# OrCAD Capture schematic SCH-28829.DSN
size B; title: FRDM-CD1030EVM; rev: A; company: Freescale Semiconductor; note: SCH-28829 PDF: SPF-28829; note: 6501 William Cannon Drive West; note: Austin, TX 78735-8598
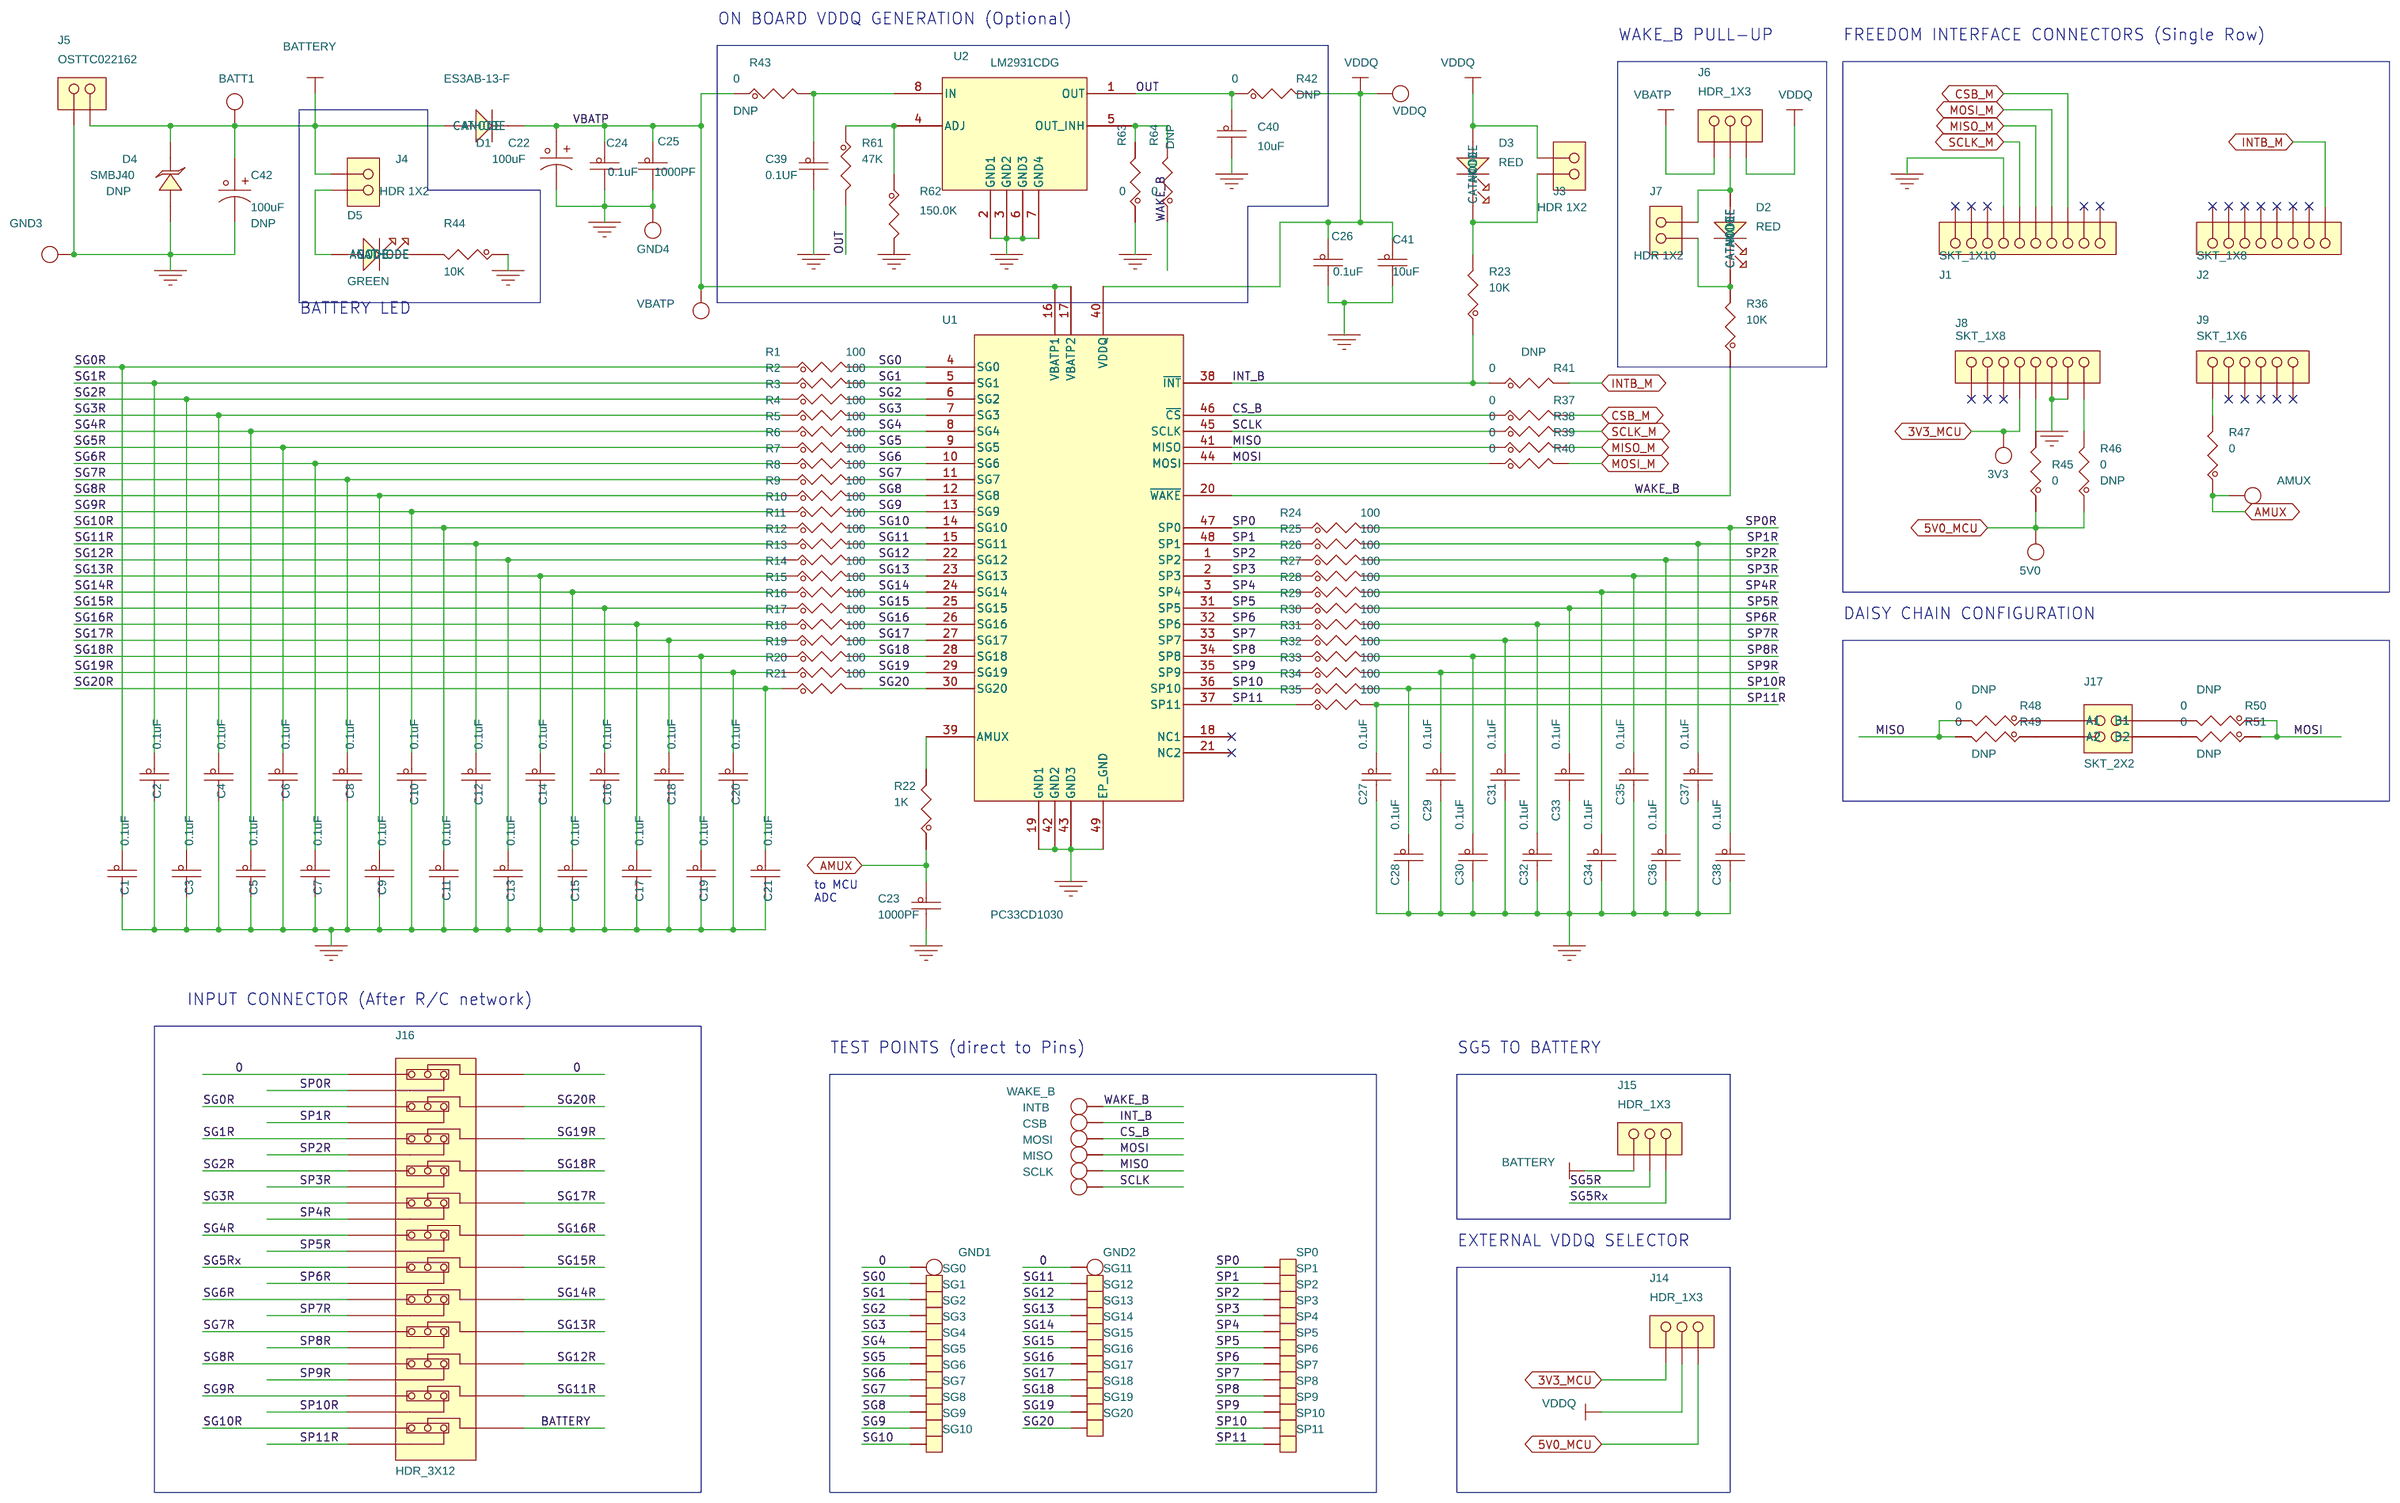
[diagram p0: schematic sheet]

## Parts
3V3  TEST POINT RED  [TEST_LOOP]
5V0  TEST POINT RED  [TEST_LOOP]
AMUX  TEST POINT RED  [TEST_LOOP]
BATT1  TEST POINT RED  [TEST_LOOP]
C1  0.1uF  [CC0603_OV]
C2  0.1uF  [CC0603_OV]
C3  0.1uF  [CC0603_OV]
C4  0.1uF  [CC0603_OV]
C5  0.1uF  [CC0603_OV]
C6  0.1uF  [CC0603_OV]
C7  0.1uF  [CC0603_OV]
C8  0.1uF  [CC0603_OV]
C9  0.1uF  [CC0603_OV]
C10  0.1uF  [CC0603_OV]
C11  0.1uF  [CC0603_OV]
C12  0.1uF  [CC0603_OV]
C13  0.1uF  [CC0603_OV]
C14  0.1uF  [CC0603_OV]
C15  0.1uF  [CC0603_OV]
C16  0.1uF  [CC0603_OV]
C17  0.1uF  [CC0603_OV]
C18  0.1uF  [CC0603_OV]
C19  0.1uF  [CC0603_OV]
C20  0.1uF  [CC0603_OV]
C21  0.1uF  [CC0603_OV]
C22  100uF  [cce8p3x8p3]
C23  1000PF  [CC0603_OV]
C24  0.1uF  [CC0603_OV]
C25  1000PF  [CC0603_OV]
C26  0.1uF  [CC0603_OV]
C27  0.1uF  [CC0603_OV]
C28  0.1uF  [CC0603_OV]
C29  0.1uF  [CC0603_OV]
C30  0.1uF  [CC0603_OV]
C31  0.1uF  [CC0603_OV]
C32  0.1uF  [CC0603_OV]
C33  0.1uF  [CC0603_OV]
C34  0.1uF  [CC0603_OV]
C35  0.1uF  [CC0603_OV]
C36  0.1uF  [CC0603_OV]
C37  0.1uF  [CC0603_OV]
C38  0.1uF  [CC0603_OV]
C39  0.1UF  [CC0603_OV]
C40  10uF  [CC1206_OV]
C41  10uF  [CC0805_OV]
C42  100uF  [cce8p3x8p3]
CSB  TEST POINT RED  [TEST_LOOP]
D1  ES3AB-13-F  [smb_4p57x3p94mm]
D2  RED  [led_2p_0805]
D3  RED  [led_2p_0805]
D4  SMBJ40  [DO-214AA_A]
D5  GREEN  [led2_2p34_2p1x1p25]
GND1  TEST POINT BLACK  [TEST_LOOP]
GND2  TEST POINT BLACK  [TEST_LOOP]
GND3  TEST POINT BLACK  [TEST_LOOP]
GND4  TEST POINT BLACK  [TEST_LOOP]
INTB  TEST POINT RED  [TEST_LOOP]
J1  SKT_1X10  [con_skt1x10_th]
J2  SKT_1X8  [con_skt1x8_th]
J3  HDR 1X2  [HDR102]
J4  HDR 1X2  [HDR102]
J5  OSTTC022162  [con2_tb_5p08_th_osttc]
J6  HDR_1X3  [HDR103]
J7  HDR 1X2  [HDR102]
J8  SKT_1X8  [con_skt1x8_th]
J9  SKT_1X6  [con_skt1x6_th]
J14  HDR_1X3  [HDR103]
J15  HDR_1X3  [HDR103]
J16  HDR_3X12  [hdr_3x12_100_th]
J17  SKT_2X2  [skt2x2_th_ssq]
MISO  TEST POINT RED  [TEST_LOOP]
MOSI  TEST POINT RED  [TEST_LOOP]
R1  100  [RC0805_OV]
R2  100  [RC0805_OV]
R3  100  [RC0805_OV]
R4  100  [RC0805_OV]
R5  100  [RC0805_OV]
R6  100  [RC0805_OV]
R7  100  [RC0805_OV]
R8  100  [RC0805_OV]
R9  100  [RC0805_OV]
R10  100  [RC0805_OV]
R11  100  [RC0805_OV]
R12  100  [RC0805_OV]
R13  100  [RC0805_OV]
R14  100  [RC0805_OV]
R15  100  [RC0805_OV]
R16  100  [RC0805_OV]
R17  100  [RC0805_OV]
R18  100  [RC0805_OV]
R19  100  [RC0805_OV]
R20  100  [RC0805_OV]
R21  100  [RC0805_OV]
R22  1K  [RC0805_OV]
R23  10K  [RC0805_OV]
R24  100  [RC0805_OV]
R25  100  [RC0805_OV]
R26  100  [RC0805_OV]
R27  100  [RC0805_OV]
R28  100  [RC0805_OV]
R29  100  [RC0805_OV]
R30  100  [RC0805_OV]
R31  100  [RC0805_OV]
R32  100  [RC0805_OV]
R33  100  [RC0805_OV]
R34  100  [RC0805_OV]
R35  100  [RC0805_OV]
R36  10K  [RC0805_OV]
R37  0  [RC0603_OV]
R38  0  [RC0603_OV]
R39  0  [RC0603_OV]
R40  0  [RC0603_OV]
R41  0  [RC0603_OV]
R42  0  [RC0603_OV]
R43  0  [RC0603_OV]
R44  10K  [RC0805_OV]
R45  0  [RC0603_OV]
R46  0  [RC0603_OV]
R47  0  [RC0603_OV]
R48  0  [RC0603_OV]
R49  0  [RC0603_OV]
R50  0  [RC0603_OV]
R51  0  [RC0603_OV]
R61  47K  [RC0603_OV]
R62  150.0K  [RC0603_OV]
R63  0  [RC0603_OV]
R64  0  [RC0603_OV]
SCLK  TEST POINT RED  [TEST_LOOP]
SG0  TH  [mst_testpoint]
SG1  TH  [mst_testpoint]
SG2  TH  [mst_testpoint]
SG3  TH  [mst_testpoint]
SG4  TH  [mst_testpoint]
SG5  TH  [mst_testpoint]
SG6  TH  [mst_testpoint]
SG7  TH  [mst_testpoint]
SG8  TH  [mst_testpoint]
SG9  TH  [mst_testpoint]
SG10  TH  [mst_testpoint]
SG11  TH  [mst_testpoint]
SG12  TH  [mst_testpoint]
SG13  TH  [mst_testpoint]
SG14  TH  [mst_testpoint]
SG15  TH  [mst_testpoint]
SG16  TH  [mst_testpoint]
SG17  TH  [mst_testpoint]
SG18  TH  [mst_testpoint]
SG19  TH  [mst_testpoint]
SG20  TH  [mst_testpoint]
SP0  TH  [mst_testpoint]
SP1  TH  [mst_testpoint]
SP2  TH  [mst_testpoint]
SP3  TH  [mst_testpoint]
SP4  TH  [mst_testpoint]
SP5  TH  [mst_testpoint]
SP6  TH  [mst_testpoint]
SP7  TH  [mst_testpoint]
SP8  TH  [mst_testpoint]
SP9  TH  [mst_testpoint]
SP10  TH  [mst_testpoint]
SP11  TH  [mst_testpoint]
U1  PC33CD1030  [LQFP48_EP146MIL]
U2  LM2931CDG  [SO8_1P27_4X5]
VBATP  TEST POINT RED  [TEST_LOOP]
VDDQ  TEST POINT RED  [TEST_LOOP]
WAKE_B  TEST POINT RED  [TEST_LOOP]

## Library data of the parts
3V3 5V0 AMUX BATT1 CSB INTB MISO MOSI SCLK VBATP VDDQ WAKE_B = TestLoop: TEST POINT RED 40 MIL DRILL 180 MIL TH 109L; AGILE_PN: 210-75684; CAD_APPROVED: Yes; HEIGHT: 4.8 MM; MFG_NAME01: KEYSTONE ELECTRONICS; MFG_PN01: 5000; ROHS: Yes
C1-C21 C24 C26-C38 = CAP_NP: CAP CER 0.1uF 100V X7R 10% 0603; AGILE_PN: 150-79200; CAD_APPROVED: Yes; FPLIST: CC0603_OV,CC0603,0603_CC; HEIGHT: 0.9MM; MFG_NAME01: Murata; MFG_PN01: GRM188R72A104KA35D; ROHS: Yes; Tolerance: 10%; VOLTAGE: 100V
C22 = CAP_POL: CAP ALEL 100uF 50V 20% -- SMD; AGILE_PN: 150-79137; CAD_APPROVED: Yes; HEIGHT: 10.5MM; MFG_NAME01: NICHICON; MFG_PN01: UUD1H101MNL1GS; ROHS: Yes; Tolerance: 20%; VOLTAGE: 50V
C23 C25 = CAP_NP: CAP CER 1000PF 100V 10% X7R 0603; AGILE_PN: 150-77156; CAD_APPROVED: Yes; FPLIST: CC0603_OV,CC0603,0603_CC; HEIGHT: 0.95MM; MFG_NAME01: KEMET; MFG_PN01: C0603C102K1RACTU; ROHS: Yes; Tolerance: 10%; VOLTAGE: 100V
C39 = CAP_NP: CAP CER 0.1UF 50V 10% X7R 0603; AGILE_PN: 150-75142; CAD_APPROVED: Yes; FPLIST: CC0603_OV,CC0603,0603_CC; HEIGHT: 0.9652MM; MFG_NAME01: AVX; MFG_PN01: 06035C104KAT2A; ROHS: Yes; Tolerance: 10%; VOLTAGE: 50V
C40 = CAP_NP: CAP CER 10uF 25V 10% X7R 1206; AGILE_PN: 150-79147; CAD_APPROVED: Yes; FPLIST: CC1206_OV,CC1206,1206_CC; HEIGHT: 1.8MM; MFG_NAME01: Murata; MFG_PN01: GRM31CR71E106KA12; ROHS: Yes; Tolerance: 10%; VOLTAGE: 25V
C41 = CAP_NP: CAP CER 10UF 16V +80/-20% Y5V 0805; AGILE_PN: 150-78869; CAD_APPROVED: Yes; FPLIST: CC0805_OV,CC0805,0805_CC; HEIGHT: 1.35MM; MFG_NAME01: MURATA; MFG_PN01: GRM21BF51C106ZE15L; ROHS: Yes; Tolerance: +80/-20%; VOLTAGE: 16V
C42 = CAP_POL: CAP ALEL 100uF 50V 20% -- SMD; AGILE_PN: 150-79137; ASSY_OPT: DNP; CAD_APPROVED: Yes; HEIGHT: 10.5MM; MFG_NAME01: NICHICON; MFG_PN01: UUD1H101MNL1GS; ROHS: Yes; Tolerance: 20%; VOLTAGE: 50V
D1 = DIODE: DIODE RECT 3A 50V AEC-Q101 SMB; AGILE_PN: 480-78596; CAD_APPROVED: Yes; HEIGHT: 2.5MM; MFG_NAME01: DIODES INC; ROHS: Yes
D2 D3 = LED: LED RED SGL 2MA 0805 SMT; AGILE_PN: 370-76492; CAD_APPROVED: Yes; HEIGHT: 0.9 MM; MFG_NAME01: ROHM; MFG_PN01: SML-211UTT86J; ROHS: Yes
D4 = DIODE_TVS: DIODE TVS 9.3A 40V SMB SMT; AGILE_PN: 480-78239; ASSY_OPT: DNP; CAD_APPROVED: Yes; HEIGHT: 2.62MM; MFG_NAME01: BOURNS; MFG_PN01: SMBJ40A; ROHS: Yes
D5 = LED: LED GRN SGL 25MA 0805; AGILE_PN: 370-76437; CAD_APPROVED: Yes; HEIGHT: 0.8MM; MFG_NAME01: Dialight; MFG_PN01: 598-8170-107F; ROHS: Yes
GND1-GND4 = TestLoop: TEST POINT BLACK 40 MIL DRILL 180 MIL TH 109L; AGILE_PN: 210-75683; CAD_APPROVED: Yes; HEIGHT: 4.8mm; MFG_NAME01: KEYSTONE ELECTRONICS; MFG_PN01: 5001; ROHS: Yes
J1 = CONN_HDR_10X1: CON 1X10 SKT TH 100MIL SP 340H SN 394L; AGILE_PN: 210-80905; CAD_APPROVED: Yes; HEIGHT: 8.636MM; MFG_NAME01: Samtec; MFG_PN01: SSQ-110-23-T-S; ROHS: Yes
J2 J8 = CONN_HDR_8X1: CON 1X8 SKT TH 100MIL SP 340H SN 394L; AGILE_PN: 210-80906; CAD_APPROVED: Yes; HEIGHT: 8.636MM; MFG_NAME01: Samtec; MFG_PN01: SSQ-108-23-T-S; ROHS: Yes
J3 J4 J7 = CONN_HDR_2X1: HDR 1X2 TH 100MIL SP 338H AU 100L; AGILE_PN: 210-80733; CAD_APPROVED: Yes; HEIGHT: 8.58MM; MFG_NAME01: SAMTEC; MFG_PN01: TSW-102-07-F-S; ROHS: Yes
J5 = CONN_HDR_2X1: CON 1X2 TB 5.08MM SP 406H SN 138L; AGILE_PN: 210-80384; CAD_APPROVED: Yes; HEIGHT: 10.3MM; MFG_NAME01: ON-SHORE TECHNOLOGY; ROHS: Yes
J6 J14 J15 = CONN_HDR_3X1: HDR 1X3 TH 100MIL SP 330H AU 98L; AGILE_PN: 210-75442; CAD_APPROVED: Yes; HEIGHT: 8.38 MM; MFG_NAME01: SAMTEC; MFG_PN01: HTSW-103-07-S-S; ROHS: Yes
J9 = CONN_HDR_6X1: CON 1X6 SKT TH 100MIL SP 340H SN 394L; AGILE_PN: 210-80907; CAD_APPROVED: Yes; HEIGHT: 8.636MM; MFG_NAME01: Samtec; MFG_PN01: SSQ-106-23-T-S; ROHS: Yes
J16 = HDR-3X12: HDR 3X12 TH 100MIL CTR 338H AU 100L; AGILE_PN: 210-79916; CAD_APPROVED: Yes; HEIGHT: 8.58MM; MFG_NAME01: SAMTEC; MFG_PN01: TSW-112-07-S-T; ROHS: Yes
J17 = CONN_HDR_2X2: CON 2X2 SKT TH 100MIL CTR 340H SN 394L; AGILE_PN: 210-80908; CAD_APPROVED: Yes; HEIGHT: 8.636MM; MFG_NAME01: Samtec; MFG_PN01: SSQ-102-23-T-D; ROHS: Yes
R1-R21 R24-R35 = RES: RES MF 100 OHM 1/2W 1% AEC-Q200 0805; AGILE_PN: 470-80989; CAD_APPROVED: Yes; FPLIST: RC0805_OV,RC0805,0805_CC; HEIGHT: 0.7 MM; MFG_NAME01: Panasonic; MFG_PN01: ERJ-P06F1000V; ROHS: Yes; Tolerance: 1%
R22 = RES: RES MF 1K 1/8W 5% 0805; AGILE_PN: 470-80854; CAD_APPROVED: Yes; FPLIST: RC0805_OV,RC0805,0805_CC; HEIGHT: 0.6 MM; MFG_NAME01: YAGEO AMERICA; MFG_PN01: RC0805JR-071KL; ROHS: Yes; Tolerance: 5%
R23 R36 R44 = RES: RES MF 10K 1/10W 5% 0805; AGILE_PN: 470-76613; CAD_APPROVED: Yes; FPLIST: RC0805_OV,RC0805,0805_CC; HEIGHT: 0.55MM; MFG_NAME01: SMEC; MFG_PN01: RC73L2A103JTF; ROHS: Yes; Tolerance: 5%
R37-R40 R45 R47 R63 = RES: RES MF ZERO OHM 1/10W -- 0603; AGILE_PN: 470-80866; FPLIST: RC0603_OV,RC0603,R603-X2,0603_CC; HEIGHT: 0.6MM; MFG_NAME01: BOURNS; MFG_PN01: CR0603J/000ELF; ROHS: Yes
R41-R43 R46 R48-R51 R64 = RES: RES MF ZERO OHM 1/10W -- 0603; AGILE_PN: 470-80866; ASSY_OPT: DNP; FPLIST: RC0603_OV,RC0603,R603-X2,0603_CC; HEIGHT: 0.6MM; MFG_NAME01: BOURNS; MFG_PN01: CR0603J/000ELF; ROHS: Yes
R61 = RES: RES MF 47K 1/16W 5% 0603; AGILE_PN: 470-30202; CAD_APPROVED: Yes; FPLIST: RC0603_OV,RC0603,0603_CC; HEIGHT: 0.55MM; MFG_NAME01: SMEC; MFG_PN01: RC73L2X473JTF; ROHS: Yes; Tolerance: 5%
R62 = RES: RES MF 150.0K 1/10W 1% 0603; AGILE_PN: 470-78114; CAD_APPROVED: Yes; FPLIST: RC0603_OV,RC0603,0603_CC; HEIGHT: 0.55MM; MFG_NAME01: KOA SPEER; MFG_PN01: RK73H1JTTD1503F; ROHS: Yes; Tolerance: 1%
SG0-SG20 SP0-SP11 = T_POINT_S: TEST POINT PAD 080-040MIL TH, NO PART TO ORDER; AGILE_PN: 210-79435; CAD_APPROVED: Yes; HEIGHT: 0.1MM; MFG_NAME01: Not a component; MFG_PN01: Not a component; ROHS: Yes
U1 = CD1030_LQFP48_EP: IC 33-CHANNEL MULTIPLE SW DETECTION INTERFACE 3.3V LQFP48; AGILE_PN: TMP-WF-24320; CAD_APPROVED: Yes; HEIGHT: 1.6MM; MFG_NAME01: FREESCALE SEMICONDUCTOR; MFG_PN01: PC33CD1030AE; PRE_APN: 312-81187; ROHS: Yes
U2 = LM2931_SO8: IC VREG LDO ADJ 2.7-29.5V 0.1A SOIC8; AGILE_PN: 315-78980; CAD_APPROVED: Yes; HEIGHT: 1.75MM; MFG_NAME01: ON SEMICONDUCTOR; ROHS: Yes

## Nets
3V3_MCU: 3V3.1(Pin1) J8.4 J14.1
5V0_MCU: 5V0.1(Pin1) J14.3 R45.1 R46.1
VBATP: C22.1 C24.1 C25.1 D1.C(CATHODE) J6.1 R43.1 U1.16(VBATP1) U1.17(VBATP2) VBATP.1(Pin1)
VDDQ: C26.1 C41.1 D3.A(ANODE) J3.1 J6.3 J14.2 R42.2 U1.40(VDDQ) VDDQ.1(Pin1)
0: C1.2 C2.2 C3.2 C4.2 C5.2 C6.2 C7.2 C8.2 C9.2 C10.2 C11.2 C12.2 C13.2 C14.2 C15.2 C16.2 C17.2 C18.2 C19.2 C20.2 C21.2 C22.2 C23.2 C24.2 C25.2 C26.2 C27.2 C28.2 C29.2 C30.2 C31.2 C32.2 C33.2 C34.2 C35.2 C36.2 C37.2 C38.2 C39.2 C40.2 C41.2 C42.2 D4.A GND1.1(Pin1) GND2.1(Pin1) GND3.1(Pin1) GND4.1(Pin1) J1.7 J5.1 J8.6 J8.7 J16.1 J16.2 R44.1 R62.2 R63.1 U1.19(GND1) U1.42(GND2) U1.43(GND3) U1.49(EP_GND) U2.2(GND1) U2.3(GND2) U2.6(GND3) U2.7(GND4)
AMUX: AMUX.1(Pin1) C23.1 R22.1 R47.1
BATTERY: BATT1.1(Pin1) C42.1 D1.A(ANODE) D4.C J4.1 J5.2 J15.1 J16.35
CS_B: CSB.1(Pin1) R37.1 U1.46(~{CS})
CSB_M: J1.3 R37.2
INT_B: INTB.1(Pin1) R23.1 R41.1 U1.38(~{INT})
INTB_M: J2.1 R41.2
MISO: MISO.1(Pin1) R39.1 R48.2 R49.2 U1.41(MISO)
MISO_M: J1.5 R39.2
MOSI: MOSI.1(Pin1) R40.1 R50.1 R51.1 U1.44(MOSI)
MOSI_M: J1.4 R40.2
OUT: C40.1 R42.1 R61.2 U2.1(OUT)
SCLK: R38.1 SCLK.1(Pin1) U1.45(SCLK)
SCLK_M: J1.6 R38.2
SG0: R1.2 SG0.1(TP) U1.4(SG0)
SG0R: C1.1 J16.4 R1.1
SG1: R2.2 SG1.1(TP) U1.5(SG1)
SG1R: C2.1 J16.7 R2.1
SG2: R3.2 SG2.1(TP) U1.6(SG2)
SG2R: C3.1 J16.10 R3.1
SG3: R4.2 SG3.1(TP) U1.7(SG3)
SG3R: C4.1 J16.13 R4.1
SG4: R5.2 SG4.1(TP) U1.8(SG4)
SG4R: C5.1 J16.16 R5.1
SG5: R6.2 SG5.1(TP) U1.9(SG5)
SG5R: C6.1 J15.2 R6.1
SG5Rx: J15.3 J16.19
SG6: R7.2 SG6.1(TP) U1.10(SG6)
SG6R: C7.1 J16.22 R7.1
SG7: R8.2 SG7.1(TP) U1.11(SG7)
SG7R: C8.1 J16.25 R8.1
SG8: R9.2 SG8.1(TP) U1.12(SG8)
SG8R: C9.1 J16.28 R9.1
SG9: R10.2 SG9.1(TP) U1.13(SG9)
SG9R: C10.1 J16.31 R10.1
SG10: R11.2 SG10.1(TP) U1.14(SG10)
SG10R: C11.1 J16.34 R11.1
SG11: R12.2 SG11.1(TP) U1.15(SG11)
SG11R: C12.1 J16.32 R12.1
SG12: R13.2 SG12.1(TP) U1.22(SG12)
SG12R: C13.1 J16.29 R13.1
SG13: R14.2 SG13.1(TP) U1.23(SG13)
SG13R: C14.1 J16.26 R14.1
SG14: R15.2 SG14.1(TP) U1.24(SG14)
SG14R: C15.1 J16.23 R15.1
SG15: R16.2 SG15.1(TP) U1.25(SG15)
SG15R: C16.1 J16.20 R16.1
SG16: R17.2 SG16.1(TP) U1.26(SG16)
SG16R: C17.1 J16.17 R17.1
SG17: R18.2 SG17.1(TP) U1.27(SG17)
SG17R: C18.1 J16.14 R18.1
SG18: R19.2 SG18.1(TP) U1.28(SG18)
SG18R: C19.1 J16.11 R19.1
SG19: R20.2 SG19.1(TP) U1.29(SG19)
SG19R: C20.1 J16.8 R20.1
SG20: R21.2 SG20.1(TP) U1.30(SG20)
SG20R: C21.1 J16.5 R21.1
SP0: R24.1 SP0.1(TP) U1.47(SP0)
SP0R: C38.1 J16.3 R24.2
SP1: R25.1 SP1.1(TP) U1.48(SP1)
SP1R: C37.1 J16.6 R25.2
SP2: R26.1 SP2.1(TP) U1.1(SP2)
SP2R: C36.1 J16.9 R26.2
SP3: R27.1 SP3.1(TP) U1.2(SP3)
SP3R: C35.1 J16.12 R27.2
SP4: R28.1 SP4.1(TP) U1.3(SP4)
SP4R: C34.1 J16.15 R28.2
SP5: R29.1 SP5.1(TP) U1.31(SP5)
SP5R: C33.1 J16.18 R29.2
SP6: R30.1 SP6.1(TP) U1.32(SP6)
SP6R: C32.1 J16.21 R30.2
SP7: R31.1 SP7.1(TP) U1.33(SP7)
SP7R: C31.1 J16.24 R31.2
SP8: R32.1 SP8.1(TP) U1.34(SP8)
SP8R: C30.1 J16.27 R32.2
SP9: R33.1 SP9.1(TP) U1.35(SP9)
SP9R: C29.1 J16.30 R33.2
SP10: R34.1 SP10.1(TP) U1.36(SP10)
SP10R: C28.1 J16.33 R34.2
SP11: R35.1 SP11.1(TP) U1.37(SP11)
SP11R: C27.1 J16.36 R35.2
WAKE_B: R36.1 R64.1 U1.20(~{WAKE}) WAKE_B.1(Pin1)
N46347: R22.2 U1.39(AMUX)
N63980: D2.A(ANODE) J6.2 J7.1
N64526: D2.C(CATHODE) J7.2 R36.2
N74267: D3.C(CATHODE) J3.2 R23.2
N81888: D5.A(ANODE) J4.2
N159644: J8.5 R45.2
N159652: J8.8 R46.2
N165115: J9.1 R47.2
N222829: C39.1 R43.2 U2.8(IN)
N224295: R61.1 R62.1 U2.4(ADJ)
N235544: R63.2 R64.2 U2.5(OUT_INH)
N266390: J17.4(B2) R51.2
N266391: J17.3(A2) R49.1
N266392: J17.2(B1) R50.2
N266393: J17.1(A1) R48.1
N266394: D5.C(CATHODE) R44.2

Not connected (* = marked no-connect by the designer): J1 1* 2* 8* 9* 10*; J2 2* 3* 4* 5* 6* 7* 8*; J8 1* 2* 3*; J9 2* 3* 4* 5* 6*; U1 18(NC1)* 21(NC2)*

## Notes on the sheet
- ON BOARD VDDQ GENERATION (Optional)
- WAKE_B PULL-UP
- FREEDOM INTERFACE CONNECTORS (Single Row)
- BATTERY LED
- DAISY CHAIN CONFIGURATION
- to MCU
  ADC
- INPUT CONNECTOR (After R/C network)
- TEST POINTS (direct to Pins)
- SG5 TO BATTERY
- EXTERNAL VDDQ SELECTOR
